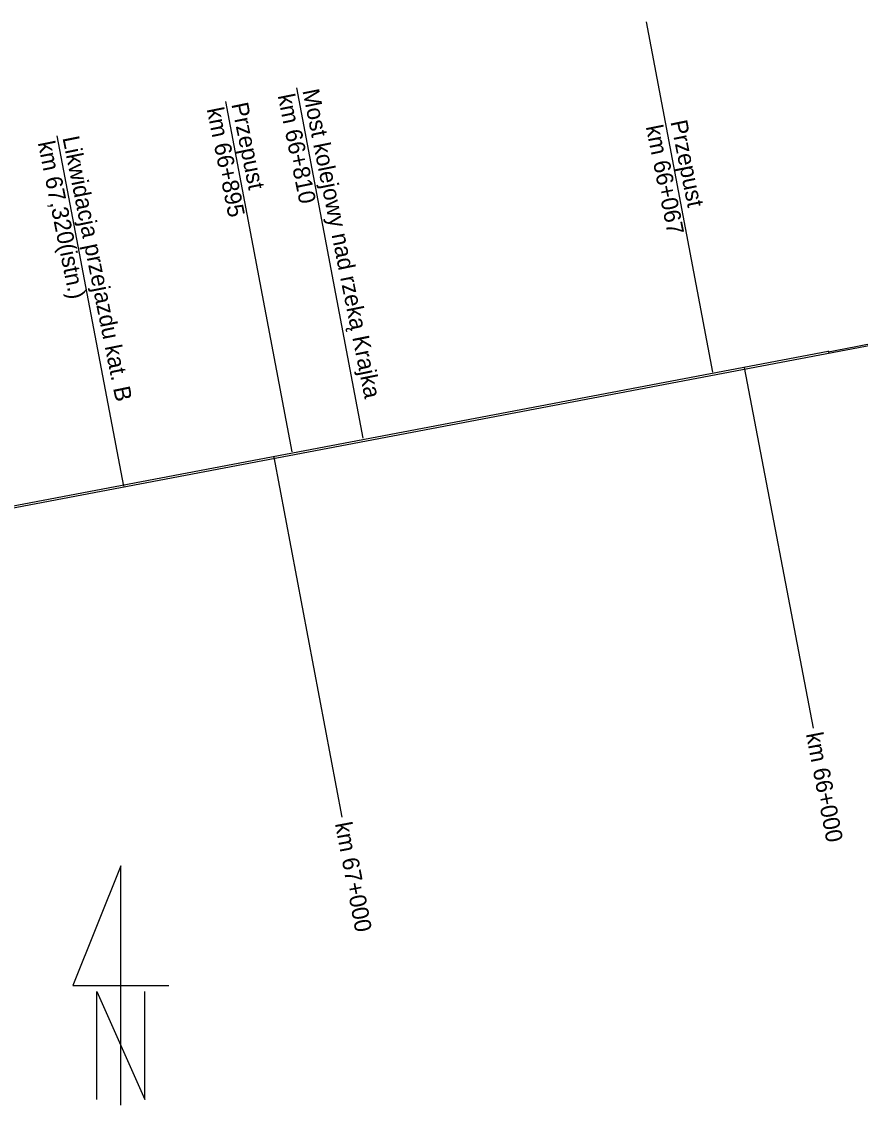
# Model space of a CAD drawing. Extents: x 6540402 to 6566579, y 5525343 to 5532423.
# Drawn here: x 6551666 to 6553417, y 5526328 to 5528591 of the extents above; entities that cross this region are included whole.
import ezdxf

# ---------------------------------------------------------------- set-up
doc = ezdxf.new("R2010")
doc.units = 0
for name, color, linetype in [('IR_default', 7, 'Continuous'), ('TOR_PS_OPIS_T-hektometry projektowane', 7, 'Continuous'), ('TOR_PS_OPIS_T-opisy dodatkowe', 7, 'Continuous'), ('TOR_PS_OPIS_T-symbole geometrii', 7, 'Continuous'), ('TOR_PS_T-tory projektowane', 7, 'Continuous')]:
    doc.layers.add(name, color=color, linetype=linetype)

msp = doc.modelspace()

# ---------------------------------------------------------------- linework, layer by layer
at = {"layer": 'IR_default'}
for p, q in [((6551823.5, 5526340.1), (6551823.5, 5526565.1)), ((6551823.5, 5526565.1), (6551923.5, 5526340.1)), ((6551923.5, 5526340.1), (6551923.5, 5526565.1))]:
    msp.add_line(p, q, dxfattribs=at)
msp.add_lwpolyline([(6551873.5, 5526327.6), (6551873.5, 5526827.6), (6551773.5, 5526577.6), (6551973.5, 5526577.6)], dxfattribs=at)
at = {"layer": 'TOR_PS_OPIS_T-hektometry projektowane'}
for points in [[(6553175.2, 5527868.9), (6553318.7, 5527115.6)], [(6552192.9, 5527681.6), (6552335.2, 5526929.3)]]:
    msp.add_lwpolyline(points, dxfattribs=at)
at = {"layer": 'TOR_PS_OPIS_T-opisy dodatkowe'}
for p, q in [((6552970.2, 5528591.2), (6553108.9, 5527859.2)), ((6552240.3, 5528452.8), (6552379, 5527720.9)), ((6552092, 5528424.7), (6552230.7, 5527692.8)), ((6551740, 5528352.7), (6551878.7, 5527620.7))]:
    msp.add_line(p, q, dxfattribs=at)
at = {"layer": 'TOR_PS_OPIS_T-symbole geometrii'}
for p, q in [((6553350.2, 5527903.3), (6553350.8, 5527900.4)), ((6553350.8, 5527900.4), (6553352.2, 5527900.7))]:
    msp.add_line(p, q, dxfattribs=at)
at = {"layer": 'TOR_PS_T-tory projektowane'}
for p, q in [((6556358, 5528467.8), (6550837.1, 5527421.3)), ((6553350.5, 5527901.9), (6551210.3, 5527496.2))]:
    msp.add_line(p, q, dxfattribs=at)
msp.add_arc((6549905.1, 5546078.2), 18500, 280.73324, 281.27525, dxfattribs=at)

# ---------------------------------------------------------------- texts
at = {"layer": 'TOR_PS_OPIS_T-hektometry projektowane'}
for s, rotation, p in [('km 66+000', 280.7814, (6553303.7, 5527103.4)), ('km 67+000', 280.7075, (6552320.4, 5526916))]:
    msp.add_text(s, height=35, rotation=rotation, dxfattribs=at).set_placement(p)
at = {"layer": 'TOR_PS_OPIS_T-opisy dodatkowe'}
for s, p in [('Most kolejowy nad rzeką Krajka', (6552252.4, 5528447.1)), ('km 66+810', (6552200.9, 5528436.7)), ('km 66+895', (6552052.6, 5528408.5)), ('Przepust', (6552104.1, 5528418.9)), ('Przepust', (6553020.8, 5528382.2)), ('km 66+067', (6552969.4, 5528371.8)), ('km 67,320(istn.)', (6551700, 5528338.3)), ('Likwidacja przejazdu kat. B', (6551751.5, 5528348.7))]:
    msp.add_text(s, height=35, rotation=281.4331, dxfattribs=at).set_placement(p)

doc.saveas('drawing.dxf')
